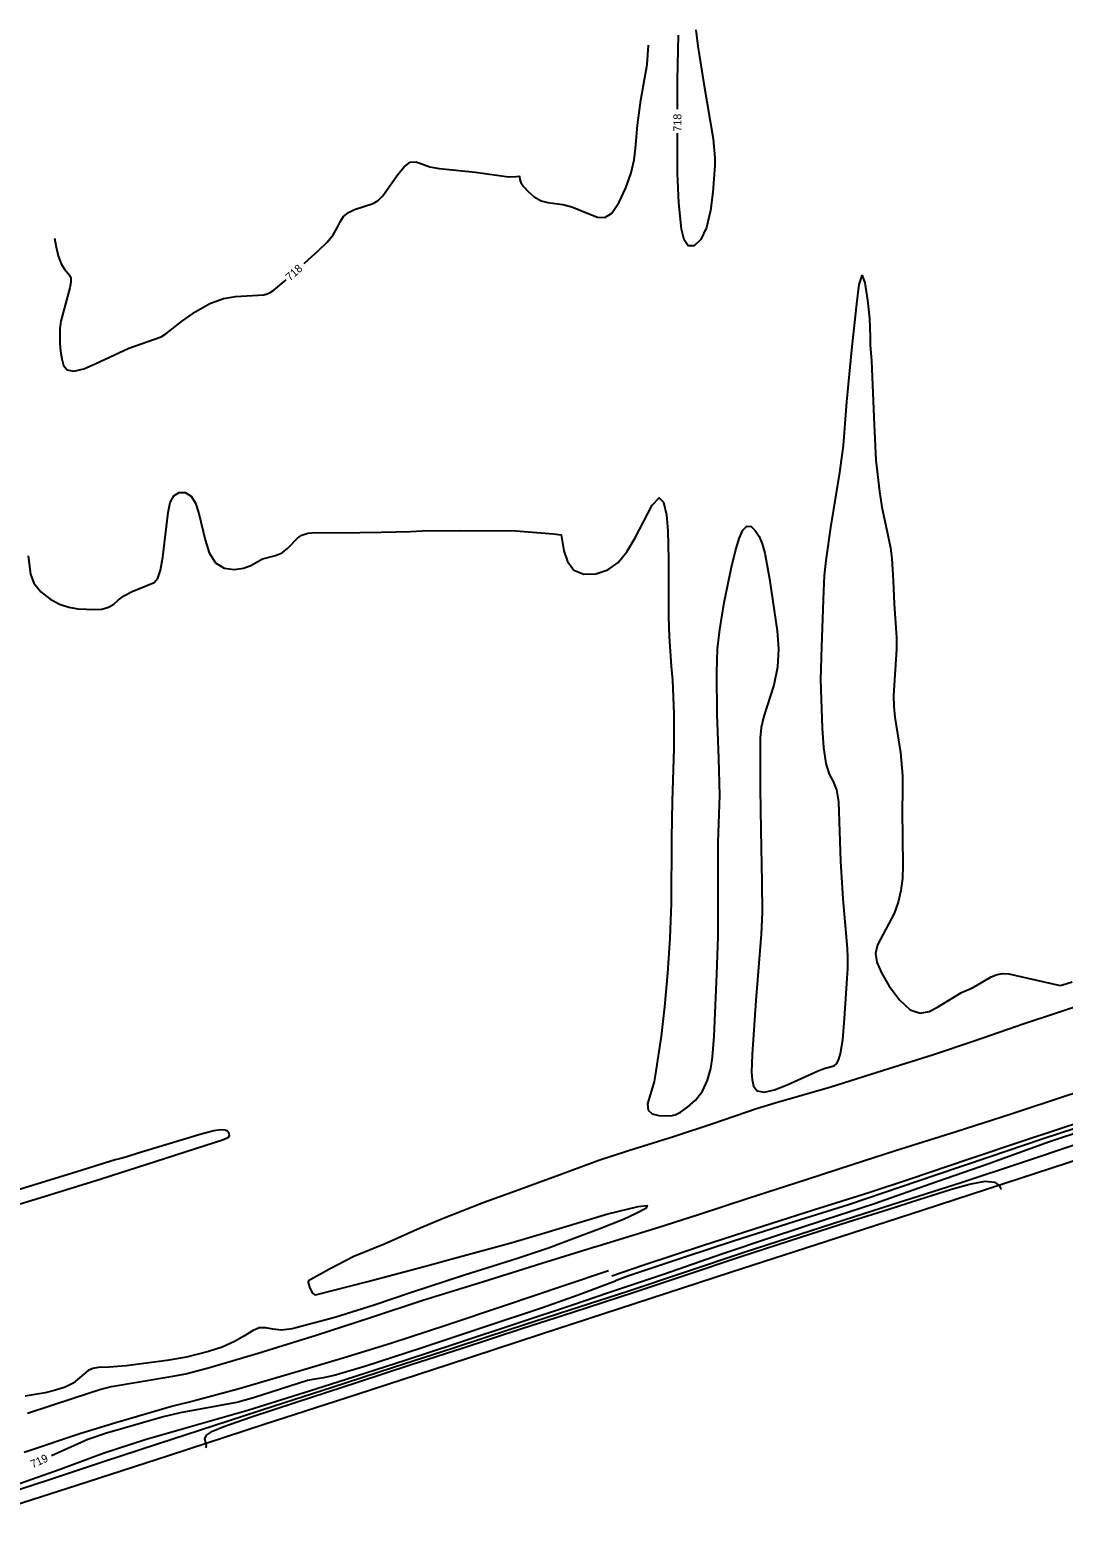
# Model space of a CAD drawing. Extents: x -361782338 to 28259792, y -263199453 to 8342113.
# Drawn here: x 1404659 to 1405176, y 576685 to 577427 of the extents above; entities that cross this region are included whole.
import ezdxf

# ---------------------------------------------------------------- set-up
doc = ezdxf.new("R2010")
doc.units = 0
for name, color, linetype in [('DT_X_Contour_Minor', 7, 'Continuous'), ('Level 14', 7, 'Continuous'), ('Level 19', 7, 'Continuous')]:
    doc.layers.add(name, color=color, linetype=linetype)

msp = doc.modelspace()

# ---------------------------------------------------------------- linework, layer by layer
at = {"layer": 'DT_X_Contour_Minor'}
for points in [[(1404992.32, 577427.37), (1404993.35, 577419.2), (1404996.32, 577400.34), (1405000.88, 577372.85), (1405001.73, 577363.33), (1405001.7, 577359.45), (1405000.76, 577346.17), (1404999.65, 577337.07), (1404997.69, 577328.56), (1404994.76, 577322.51), (1404991.44, 577319.4), (1404988.48, 577319.39), (1404986.45, 577322.4), (1404985.2, 577327.62), (1404983.8, 577340.9), (1404983.08, 577355.46), (1404983.07, 577375.66)], [(1404796.5, 577310.52), (1404804.08, 577317.34), (1404807.98, 577321.15), (1404811.01, 577324.79), (1404813.03, 577328.25), (1404814.55, 577331.38), (1404816.26, 577334.02), (1404818.68, 577336.02), (1404821.65, 577337.5), (1404830.96, 577340.5), (1404833.6, 577341.99), (1404835.88, 577344.24), (1404840.47, 577350.92), (1404843.33, 577355.06), (1404846.45, 577358.8), (1404849.55, 577361.12), (1404852.48, 577361.36), (1404859.27, 577358.84), (1404863.94, 577357.98), (1404882.18, 577356.17), (1404898.67, 577353.76), (1404902.53, 577353.95), (1404904.09, 577354.09), (1404904.31, 577352.49), (1404904.86, 577351.04), (1404906.17, 577349.01), (1404908.49, 577346.44), (1404911.54, 577343.86), (1404914.92, 577341.88), (1404918.34, 577340.92), (1404925.85, 577339.97), (1404930.26, 577338.75), (1404939.25, 577335.18), (1404943.17, 577333.67), (1404946.77, 577333.48), (1404950.33, 577335.74), (1404953.98, 577341.09), (1404957.35, 577348.34), (1404959.94, 577355.82), (1404961.43, 577362.25), (1404962.14, 577367.95), (1404963.12, 577379.72), (1404964.75, 577392.06), (1404968.04, 577410.04), (1404968.71, 577419.69)], [(1404983.09, 577387.66), (1404983.14, 577402.07), (1404983.7, 577424.57)], [(1404671.86, 577323.14), (1404672.42, 577319.54), (1404673.68, 577314.3), (1404675.15, 577310.26), (1404676.72, 577307.64), (1404679.3, 577304.73), (1404679.89, 577303.23), (1404679.92, 577301.18), (1404679.36, 577298.26), (1404674.89, 577281.59), (1404674.46, 577278.03), (1404674.45, 577270.58), (1404674.79, 577266.63), (1404675.39, 577262.84), (1404676.34, 577259.55), (1404678.15, 577257.27), (1404681.39, 577256.6), (1404686.37, 577257.84), (1404692.17, 577260.27), (1404708.85, 577268.24), (1404725.06, 577273.9), (1404727.35, 577275.31), (1404735.76, 577281.89), (1404742.33, 577286.56), (1404749.42, 577290.56), (1404756.21, 577292.92), (1404762.23, 577293.95), (1404776.45, 577294.84), (1404778.03, 577295.3), (1404779.64, 577296.05), (1404781.39, 577297.21), (1404786.49, 577301.52), (1404787.57, 577302.5)], [(1404968.4, 576887.23), (1404970.5, 576885.37), (1404973.72, 576884.57), (1404979.63, 576884.43), (1404981.95, 576884.97), (1404984.65, 576886.33), (1404988.2, 576888.77), (1404992.08, 576892.29), (1404995.57, 576896.82), (1404998.08, 576902.22), (1404999.7, 576908.02), (1405000.66, 576913.7), (1405001.51, 576924.33), (1405002.85, 576955.29), (1405003.39, 576974.06), (1405003.42, 576994.05), (1405003.53, 577021.25), (1405004.29, 577044.53), (1405003.72, 577063), (1405003.02, 577085.27), (1405002.85, 577105.9), (1405003.16, 577117.88), (1405004.21, 577127.55), (1405006.46, 577141.01), (1405010.08, 577158.67), (1405012.05, 577166.81), (1405013.94, 577173.06), (1405015.8, 577177.19), (1405017.76, 577179.14), (1405019.88, 577178.96), (1405022.02, 577177.11), (1405023.93, 577174.1), (1405025.47, 577170.36), (1405026.75, 577165.73), (1405029.13, 577152.82), (1405032.92, 577126.95), (1405033.61, 577117.86), (1405033.16, 577108.73), (1405031.28, 577099.71), (1405026.32, 577084.23), (1405024.99, 577078.63), (1405024.48, 577073.32), (1405024.4, 577048.03), (1405024.69, 577027.27), (1405025.28, 577001.31), (1405025.47, 576986.15), (1405024.93, 576975.2), (1405022.2, 576942.14), (1405020.47, 576915.12), (1405020.1, 576906.19), (1405020.37, 576902.59), (1405021.18, 576899.34), (1405023.01, 576896.99), (1405026.41, 576896.21), (1405031.66, 576897.43), (1405037.95, 576899.96), (1405053.7, 576907.13), (1405057, 576908.3), (1405061.34, 576909.44), (1405062.72, 576910.56), (1405063.81, 576912.71), (1405064.65, 576915.65), (1405065.77, 576922.51), (1405066.64, 576933.02), (1405068.17, 576958.12), (1405068.31, 576963.56), (1405068.14, 576968.11), (1405065.99, 576992.98), (1405064.82, 577011.69), (1405063.8, 577041.36), (1405062.76, 577047.36), (1405061.09, 577051.49), (1405059.14, 577055.22), (1405057.39, 577060.48), (1405056.23, 577068.59), (1405055.55, 577078.3), (1405054.82, 577102.46), (1405055.18, 577119.06), (1405056.29, 577146.85), (1405056.67, 577154.46), (1405057.34, 577161.99), (1405059.83, 577178.55), (1405064.25, 577205.97), (1405066, 577219.56), (1405067.82, 577241.28), (1405070.3, 577267.3), (1405072.71, 577290.35), (1405073.94, 577299.94), (1405075.35, 577304.44), (1405076.82, 577300.83), (1405078.15, 577292.16), (1405079.06, 577283.01), (1405079.37, 577273.64), (1405079.4, 577269.87), (1405080.08, 577261.63), (1405081.49, 577229.88), (1405082.31, 577212.24), (1405084.07, 577196.49), (1405085.23, 577188.71), (1405087.55, 577177.86), (1405089.5, 577168.44)], [(1404658.54, 577164.34), (1404659.77, 577155.24), (1404661.48, 577150.64), (1404664.88, 577146.45), (1404669.43, 577142.92), (1404674.36, 577140.28), (1404679.02, 577138.69), (1404683.38, 577137.89), (1404691.69, 577137.47), (1404695.51, 577137.75), (1404698.76, 577138.64), (1404701.36, 577140.27), (1404703.8, 577142.38), (1404706.75, 577144.56), (1404710.64, 577146.53), (1404721.51, 577151), (1404723.4, 577153.17), (1404724.76, 577157.2), (1404725.91, 577163.7), (1404728.56, 577186.01), (1404729.63, 577190.98), (1404731.38, 577194.33), (1404734.04, 577196.04), (1404737.15, 577196.03), (1404740.06, 577194.22), (1404742.29, 577190.62), (1404743.99, 577185.52), (1404747.01, 577172.42), (1404749.11, 577165.91), (1404752.22, 577160.89), (1404756.59, 577158.18), (1404761.55, 577157.47), (1404766.18, 577158.14), (1404769.82, 577159.61), (1404775.68, 577162.8), (1404782.22, 577164.46), (1404785.5, 577165.8), (1404788.46, 577168.12), (1404793.42, 577173.31), (1404795.45, 577174.78), (1404798.39, 577175.74), (1404800.44, 577175.92), (1404824.39, 577176), (1404835.09, 577176.16), (1404849.73, 577176.49), (1404855.52, 577176.89), (1404874.78, 577177.03), (1404902.26, 577176.93), (1404921.17, 577175.35), (1404925.03, 577174.87), (1404926.36, 577166.82), (1404928.1, 577161.53), (1404931.33, 577157.2), (1404936.34, 577155.16), (1404942.36, 577155.36), (1404948.31, 577157.42), (1404953.39, 577161.03), (1404957.82, 577166.29), (1404962.05, 577173.4), (1404970.51, 577189.7), (1404973.9, 577193.44), (1404976.2, 577191.21), (1404977.56, 577184.78), (1404978.25, 577176.88), (1404978.57, 577162.47), (1404978.59, 577133.8), (1404978.88, 577124.02), (1404980.03, 577109.26), (1404980.63, 577102.28), (1404981.31, 577085.45), (1404981.23, 577068.02), (1404980.43, 577041.71), (1404980.14, 577023.31), (1404979.98, 576990.62), (1404979.21, 576973.21), (1404978.06, 576955.71), (1404976.59, 576939), (1404974.88, 576924.21), (1404972, 576904.63), (1404971.41, 576901.52), (1404968.15, 576890.41), (1404968.4, 576887.23)], [(1405089.5, 577168.44), (1405090.21, 577163.09), (1405090.96, 577151.81), (1405091.4, 577140.43), (1405092.58, 577123.54), (1405092.49, 577117.76), (1405091.03, 577094.61), (1405091.18, 577089.07), (1405091.8, 577083.66), (1405094.53, 577066.05), (1405095.53, 577054.52), (1405095.58, 577046.68), (1405095.47, 577037.12), (1405095.8, 577009.74), (1405095.53, 577003.14), (1405094.8, 576997.03), (1405093.46, 576991.27), (1405091.35, 576985.66), (1405083.12, 576969.88), (1405082.13, 576965.65), (1405082.72, 576961.32), (1405085.02, 576955.99), (1405088.98, 576949.2), (1405094, 576942.4), (1405099.34, 576937.48), (1405104.37, 576935.81), (1405108.95, 576936.66), (1405113.05, 576938.78), (1405125.1, 576946.14), (1405130.5, 576948.48), (1405139.92, 576953.87), (1405142.93, 576955.09), (1405145.66, 576955.58), (1405148.67, 576955.36), (1405158.25, 576953.33), (1405174.4, 576949.62), (1405175.1, 576949.72), (1405180.3, 576951.44)], [(1404940.58, 576818.62), (1404943.47, 576819.52), (1404973.37, 576828.68), (1404993.69, 576835.17), (1405018.38, 576843.3), (1405047.46, 576852.58), (1405070.35, 576860.14), (1405092.08, 576867.08), (1405122.36, 576876.53), (1405149.86, 576885.52), (1405178.1, 576894.8), (1405201.47, 576902.13), (1405229.94, 576911.05), (1405260.65, 576920.76), (1405290.61, 576930.48), (1405318.2, 576939.83), (1405346.47, 576949.16), (1405363.25, 576954.48)], [(1405187.77, 576940.76), (1405156.39, 576930.36), (1405131.44, 576921.76)], [(1405131.44, 576921.76), (1405111.08, 576914.93), (1405086.07, 576907.05), (1405059.69, 576898.84), (1405031.96, 576890.75), (1405022.61, 576887.9), (1405000.76, 576880.41), (1404981.15, 576873.89), (1404958.13, 576866.76), (1404943.8, 576862.13), (1404925.82, 576855.49), (1404903.96, 576847.48), (1404886.04, 576841), (1404865.74, 576833.01), (1404854.6, 576828.25), (1404837.08, 576820.42), (1404821.45, 576814.09), (1404809.14, 576807.74), (1404799.94, 576802.67)], [(1404651.93, 576699.89), (1404674.66, 576707.8), (1404696.08, 576715.79), (1404717.07, 576722.66), (1404736.17, 576728.19), (1404768.86, 576737.53), (1404799.18, 576747), (1404817.6, 576752.85), (1404846.99, 576762.35), (1404871.79, 576770.52), (1404904.48, 576781.22), (1404930.57, 576789.9), (1404948.62, 576796.17), (1404976.2, 576805.34), (1405005.33, 576815.47), (1405030.07, 576823.81), (1405056.94, 576832.67), (1405081.5, 576840.69), (1405109.33, 576850.52), (1405138.18, 576860.38), (1405169.03, 576871.63), (1405187.23, 576877.63)], [(1404654.64, 576840.5), (1404666.62, 576844.09), (1404695.05, 576852.94), (1404722.67, 576861.81), (1404756.17, 576872.58), (1404758.66, 576873.76), (1404759.2, 576874.62), (1404759.01, 576875.58), (1404758.77, 576876.21), (1404758.22, 576876.82), (1404757.11, 576877.29), (1404755.09, 576877.42), (1404752.4, 576877.04)], [(1404752.4, 576877.04), (1404751.39, 576876.89), (1404745.13, 576875.34), (1404725.77, 576869.39), (1404713.67, 576865.73)], [(1404950.35, 576804.51), (1404966.38, 576809.95), (1404995.19, 576819.38), (1405021.94, 576828.05), (1405051.03, 576837.44), (1405079.2, 576846.34), (1405098.86, 576852.86), (1405128.86, 576862.94), (1405156.77, 576872.21), (1405187.09, 576882.22)], [(1405190.3, 576880.95), (1405165.34, 576872.73), (1405138.88, 576863.81), (1405112.16, 576854.86), (1405086.16, 576845.91), (1405068.64, 576840.03), (1405041.87, 576831.64), (1405011.11, 576821.71), (1404987.76, 576814.1), (1404958.3, 576804.3), (1404952.1, 576801.97)], [(1404641.03, 576693.45), (1404668.73, 576702.56), (1404695.72, 576711.51), (1404723.75, 576720.67), (1404751.43, 576729.7), (1404781.53, 576739.47), (1404810.48, 576748.85), (1404841.13, 576758.8), (1404871.12, 576768.51), (1404899.99, 576777.89), (1404929.32, 576787.41), (1404958.33, 576796.85), (1404986.68, 576806.25), (1405016.97, 576816.39), (1405038.65, 576823.44), (1405066.41, 576832.43), (1405094.45, 576841.42), (1405099.73, 576843.1), (1405125.44, 576851.36), (1405154.52, 576860.91), (1405182.93, 576870.45)], [(1404699.46, 576861.58), (1404682.89, 576856.44), (1404652.1, 576846.96), (1404643.88, 576844.78)], [(1404704.29, 576862.99), (1404702.12, 576862.4), (1404699.46, 576861.58)], [(1404713.67, 576865.73), (1404707.36, 576863.82), (1404704.29, 576862.99)], [(1404747.43, 576718.5), (1404747.69, 576719.53), (1404746.91, 576723.06), (1404747.71, 576724.75), (1404750.72, 576726.75), (1404756.48, 576729.2), (1404769.68, 576733.82), (1404792.5, 576741.31), (1404823.75, 576751.54), (1404849.6, 576759.92), (1404875.45, 576768.31), (1404905.4, 576778.07), (1404930.83, 576786.35), (1404961.54, 576796.37), (1404987.41, 576805), (1405014.72, 576814.05), (1405044.59, 576823.72), (1405068.47, 576831.39), (1405088.23, 576837.67), (1405103.74, 576842.6), (1405120.03, 576847.76), (1405129.05, 576850.27), (1405136.85, 576851.7), (1405141.59, 576851.3), (1405143.82, 576849.66), (1405144.9, 576847.63)], [(1404802.28, 576795.03), (1404802.82, 576795.09), (1404827.72, 576801.38), (1404857.12, 576809.37), (1404871.75, 576813.22), (1404899.38, 576820.86), (1404915.17, 576825.46), (1404948.3, 576835.38), (1404963.55, 576839.11), (1404968.03, 576839.61), (1404967.23, 576838.2), (1404962.54, 576835.54), (1404956.21, 576832.59), (1404944.28, 576828), (1404932.28, 576823.53), (1404918.67, 576818.32), (1404903.61, 576813.24), (1404887.89, 576808.27)], [(1404658.21, 576735.81), (1404681.04, 576743.37), (1404695, 576747.74), (1404700.25, 576749.07), (1404714.1, 576751.53), (1404730.94, 576754.25), (1404737.45, 576755.53), (1404749.22, 576758.6), (1404773.61, 576765.88), (1404802.63, 576774.82), (1404829.7, 576783.64), (1404855.9, 576792.28), (1404886.12, 576801.66), (1404915.39, 576810.77), (1404940.58, 576818.62)], [(1404948.65, 576806.97), (1404925.88, 576799.34), (1404897.17, 576789.57), (1404866.81, 576779.4), (1404840.38, 576770.86), (1404818.13, 576763.89), (1404794.73, 576756.95), (1404764.03, 576747.96), (1404741.8, 576742.04), (1404730.88, 576739.23), (1404702.43, 576731.06), (1404684.97, 576725.7), (1404656.65, 576716.17)], [(1404887.89, 576808.27), (1404877.16, 576804.88), (1404849.71, 576795.95), (1404831.58, 576789.75), (1404811.82, 576783.62), (1404790.51, 576777.92), (1404785.27, 576777.35), (1404780.95, 576777.81), (1404777.34, 576778.54), (1404774.05, 576778.53), (1404770.67, 576777.04), (1404766.75, 576774.5), (1404761.78, 576771.57), (1404755.54, 576768.87), (1404748.82, 576766.61), (1404737.7, 576763.75), (1404728, 576762.22), (1404707.58, 576759.47), (1404699.15, 576758.76), (1404693.58, 576758.56), (1404691.01, 576758.15), (1404688.65, 576757.15), (1404681.13, 576750.86), (1404677.09, 576748.88), (1404672.3, 576747.26), (1404667.17, 576745.99), (1404657.19, 576744.36)], [(1404670.28, 576714.64), (1404688.38, 576722.82), (1404697.33, 576725.77), (1404725.58, 576734.02), (1404734.8, 576736.1), (1404762.93, 576741.33), (1404771.26, 576743.68), (1404798.22, 576752.25), (1404803.13, 576753.08), (1404806.45, 576753.61), (1404811.53, 576754.8), (1404827.31, 576759.55), (1404855.1, 576768.54), (1404886.55, 576778.92), (1404915.69, 576788.58), (1404933.44, 576794.97), (1404952.1, 576801.97)], [(1404799.94, 576802.67), (1404798.65, 576801.97), (1404798.55, 576801.1), (1404799.4, 576798.24), (1404800.69, 576795.83), (1404801.31, 576795.23), (1404801.96, 576795), (1404802.28, 576795.03)]]:
    msp.add_lwpolyline(points, dxfattribs=at)
at = {"layer": 'Level 14'}
msp.add_lwpolyline([(1405693.63, 577026.65), (1405647.23, 577011.88), (1405601.41, 576997.31), (1405565.47, 576986.03), (1405521.27, 576972.22), (1405477.58, 576957.8), (1405436.64, 576944.81), (1405394.97, 576931.31), (1405338.95, 576913.22), (1405293.27, 576898.15), (1405246.95, 576883.11), (1405201.35, 576868.47), (1405154.39, 576853.12), (1405105.93, 576837.31), (1405058.09, 576821.86), (1405009.55, 576806.2), (1404961.61, 576790.46), (1404915.2, 576775.33), (1404868.59, 576760), (1404822.97, 576745.16), (1404776.57, 576730.07), (1404728.75, 576714.56), (1404683.02, 576699.67), (1404638.14, 576685.26)], dxfattribs=at)

# ---------------------------------------------------------------- texts
at = {"layer": 'Level 19'}
for s, rotation, p in [('718', 89.83405, (1404985.06, 577376.41)), ('718', 41.9577, (1404789.47, 577301.52)), ('719', 24.32779, (1404660.85, 576708.18))]:
    msp.add_text(s, height=4, rotation=rotation, dxfattribs=at).set_placement(p)

doc.saveas('drawing.dxf')
